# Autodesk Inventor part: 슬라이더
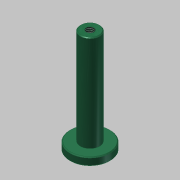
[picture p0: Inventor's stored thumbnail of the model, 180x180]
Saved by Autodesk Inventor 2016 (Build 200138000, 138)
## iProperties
Created: 2016-02
Part Number: 슬라이더
Material: 스테인리스강
Document SubType Name: Modeling
Designer: mduedu
Density: 8.08 g/cm^3
Appearance: 매끄러움 - 짙은 바다 녹색
Mass: 72.5507 g
Surface Area: 37.669 cm^2
Volume: 8.97904 cm^3
Author: mduedu
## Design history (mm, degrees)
sketch "스케치1"
  geometry: C1 r 12.5 at (0, 0); 1 further point
  constraints: 1 centre point, 1 coincident
  dimensions: "d0" = 25 diameter of C1
extrude "돌출1" new body sketch "스케치1" distance "d1" = 5; taper "d2" = 0 deg
sketch "스케치2"
  geometry: C1 r 6 at (0, 0); 1 further point
  constraints: 1 centre point, 1 coincident
  dimensions: "d3" = 12 diameter of C1
extrude "돌출2" join sketch "스케치2" distance "d4" = 60; taper "d5" = 0 deg
chamfer "모따기1" distance "d6" = 0.5; stored, may be unused: second distance "d7" = 2, angle "d8" = 45 deg
hole "구멍1" diameter "d11" = 4.917; stored, may be unused: countersink angle "d15" = 90 deg, drill point angle "d17" = 118 deg; dims "d9" = 10, "d10" = 10, "d12" = 10, "d13" = 4, "d14" = 2, "d16" = 12
chamfer "모따기2" distance "d18" = 0.5; stored, may be unused: second distance "d19" = 2, angle "d20" = 45 deg
sketch "스케치3"
  geometry: L1 (-12.5, 4.5)-(-12, 5) reference; L2 (-12, 5)-(-6, 5) reference; L3 (-6, 5)-(-6, 64.5) reference; L4 (-6, 64.5)-(-5.5, 65) reference; L5 (-5.5, 65)-(-2.458, 65) reference; L6 (-2.458, 65)-(-2.458, 53) reference; L7 (-2.458, 53)-(0, 51.523) reference; L8 (0, 51.523)-(2.458, 53) reference; L9 (2.458, 53)-(2.458, 65) reference; L10 (2.458, 65)-(5.5, 65) reference; L11 (5.5, 65)-(6, 64.5) reference; L12 (6, 64.5)-(6, 5) reference; L13 (6, 5)-(12, 5) reference; L14 (12, 5)-(12.5, 4.5) reference; L15 (12.5, 4.5)-(12.5, 0.5) reference; L16 (12.5, 0.5)-(12, 0) reference; L17 (12, 0)-(-12, 0) reference; L18 (-12, 0)-(-12.5, 0.5) reference; L19 (-12.5, 0.5)-(-12.5, 4.5) reference; 1 further point
  node "절단 모서리 투영1"
node "솔리드1"
